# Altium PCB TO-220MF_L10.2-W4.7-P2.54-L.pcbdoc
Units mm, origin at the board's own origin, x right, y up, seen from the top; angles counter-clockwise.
Board outline 24 x 17.51 mm, 2 copper layers (Top Layer, Bottom Layer), stack 0 mm thick; 1 components, 0 nets, 3 pads, 0 vias.
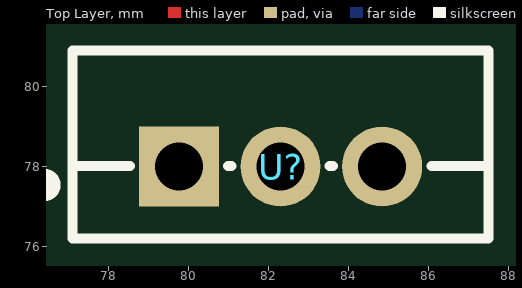
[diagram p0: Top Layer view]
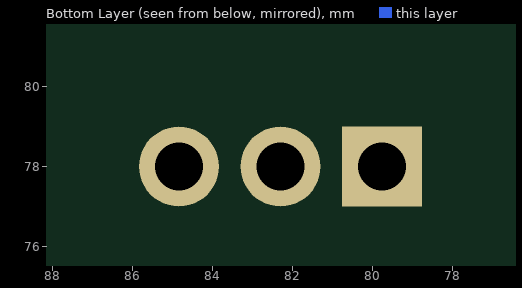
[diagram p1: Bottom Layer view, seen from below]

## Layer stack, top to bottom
Top Layer: signal copper (thickness not stored)
Bottom Layer: signal copper (thickness not stored)

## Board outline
93.847,69.85 69.85,69.85 69.85,87.36 93.847,87.36

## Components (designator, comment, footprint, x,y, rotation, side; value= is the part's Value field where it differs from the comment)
U? "" TO-220MF_L10.2-W4.7-P2.54-L 82.297,78 r0 top

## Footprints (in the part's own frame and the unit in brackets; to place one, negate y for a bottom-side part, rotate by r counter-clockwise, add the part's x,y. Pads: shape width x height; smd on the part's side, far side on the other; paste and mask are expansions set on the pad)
TO-220MF_L10.2-W4.7-P2.54-L [mm]
  rect 2x2 hole 1.2: 1(-2.54,0)
  round 2 hole 1.2: 2(0,0) 3(2.54,0)
  silkscreen extent -6.1,-1.8 5.2,2.9

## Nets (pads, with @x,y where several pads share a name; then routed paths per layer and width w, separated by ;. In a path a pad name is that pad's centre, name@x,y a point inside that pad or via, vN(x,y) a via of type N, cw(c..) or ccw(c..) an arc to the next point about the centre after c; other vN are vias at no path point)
pads on no net: U?.1 U?.2 U?.3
